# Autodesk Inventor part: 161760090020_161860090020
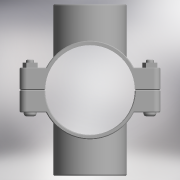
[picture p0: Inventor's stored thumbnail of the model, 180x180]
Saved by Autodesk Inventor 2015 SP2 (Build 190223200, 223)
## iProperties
Created: 2017-05
Part Number: 161760090020_161860090020
Material: Generic
Description: PLASSON DOUBLE SADDLE 90-2"
Document SubType Name: Modeling
Designer: KIM
Density: 1 g/cm^3
Appearance: Default
Author: KIM
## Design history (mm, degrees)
derived "16176.ipt"
feature "Solid1::16176.ipt"
feature "Solid2::16176.ipt"
tag "TaggingFeature1"
body "Solid1"
body "Solid2"
other parameters: "d0" = 99, "d1" = 141, "d2" = 45, "d4" = 105, "d5" = 0, "d6" = 7.05, "d7" = 141, "d8" = 0.1, "d10" = 0, "d11" = 0.9, "d20" = 0.9, "d23" = 0.9, "d36" = 13, "d37" = 10.4, "d38" = 53, "d39" = 0, "d40" = 3, "d41" = 5, "d42" = 0, "d43" = 8, "d44" = 3, "d45" = 0, "d46" = 0.9, "d52" = 56.656, "d54" = 0, "d57" = 0, "d58" = 97.2, "d60" = 0, "d62" = 13, "d63" = 10.4, "d66" = 84.2, "d67" = 172, "d68" = 73.6528, "d69" = 56.656, "d71" = 0, "d74" = 0, "d75" = 0.9, "G_" = 56.656, "A_" = 86, "L_" = 141, "L_1" = 105
